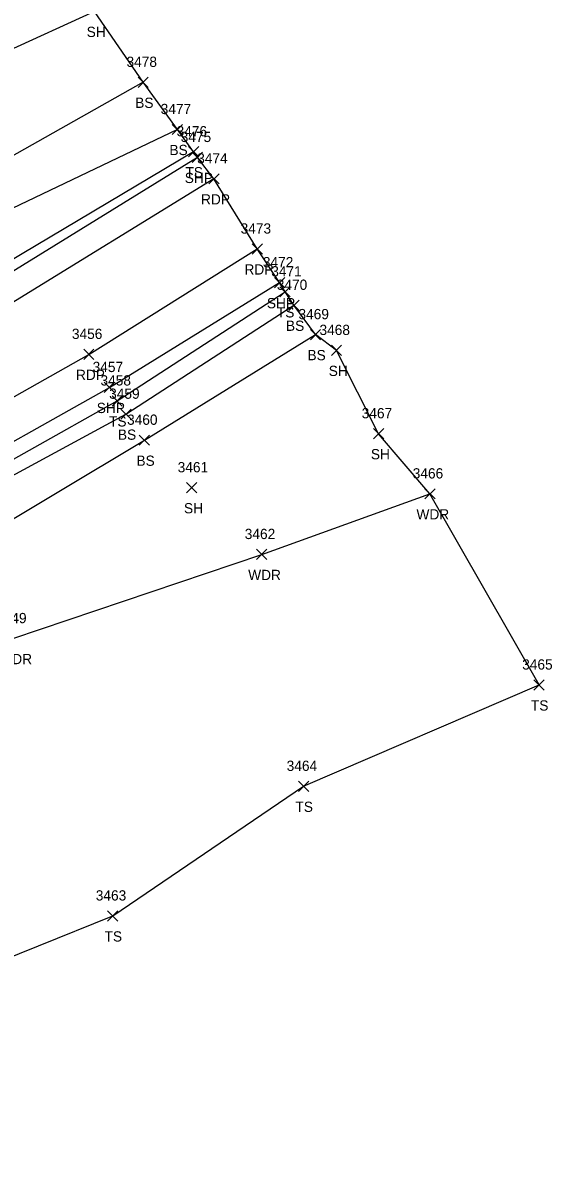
# Model space of a CAD drawing. Extents: x 1623612 to 1625808, y 621345 to 627748.
# Drawn here: x 1625436 to 1625539.3, y 626896.7 to 627120.5 of the extents above; entities that cross this region are included whole.
import ezdxf

# ---------------------------------------------------------------- set-up
doc = ezdxf.new("R2010")
doc.units = 0
for name, color, linetype in [('L_A', 7, 'Continuous'), ('L_I', 7, 'Continuous'), ('L_TIC', 7, 'Continuous'), ('LAWA', 7, 'Continuous'), ('LELB', 7, 'Continuous'), ('LSOGP', 7, 'Continuous'), ('P_A', 7, 'Continuous'), ('P_I', 7, 'Continuous'), ('P_TIC', 7, 'Continuous'), ('PET', 7, 'Continuous'), ('PSP', 7, 'Continuous')]:
    doc.layers.add(name, color=color, linetype=linetype)

msp = doc.modelspace()

# ---------------------------------------------------------------- linework, layer by layer
at = {"layer": 'L_TIC'}
for points in [[(1625458.45, 627107.93), (1625460.45, 627109.93)], [(1625460.45, 627107.93), (1625458.45, 627109.93)], [(1625465.12, 627098.72), (1625467.12, 627100.72)], [(1625467.12, 627098.72), (1625465.12, 627100.72)], [(1625468.29, 627094.38), (1625470.29, 627096.38)], [(1625470.29, 627094.38), (1625468.29, 627096.38)], [(1625486.14, 627067.05), (1625488.14, 627069.05)], [(1625488.14, 627067.05), (1625486.14, 627069.05)], [(1625487.88, 627064.43), (1625489.88, 627066.43)], [(1625489.88, 627064.43), (1625487.88, 627066.43)], [(1625492.08, 627058.7), (1625494.08, 627060.7)], [(1625494.08, 627058.7), (1625492.08, 627060.7)], [(1625496.18, 627055.62), (1625498.18, 627057.62)], [(1625498.18, 627055.62), (1625496.18, 627057.62)], [(1625453.37, 627045.77), (1625455.37, 627047.77)], [(1625455.37, 627045.77), (1625453.37, 627047.77)], [(1625455.07, 627043.18), (1625457.07, 627045.18)], [(1625457.07, 627043.18), (1625455.07, 627045.18)], [(1625504.41, 627039.37), (1625506.41, 627041.37)], [(1625506.41, 627039.37), (1625504.41, 627041.37)], [(1625458.69, 627038.1), (1625460.69, 627040.1)], [(1625460.69, 627038.1), (1625458.69, 627040.1)], [(1625467.92, 627028.83), (1625469.92, 627030.83)], [(1625469.92, 627028.83), (1625467.92, 627030.83)], [(1625514.44, 627027.63), (1625516.44, 627029.63)], [(1625516.44, 627027.63), (1625514.44, 627029.63)], [(1625481.59, 627015.81), (1625483.59, 627017.81)], [(1625483.59, 627015.81), (1625481.59, 627017.81)], [(1625535.74, 626990.35), (1625537.74, 626992.35)], [(1625537.74, 626990.35), (1625535.74, 626992.35)], [(1625489.76, 626970.58), (1625491.76, 626972.58)], [(1625491.76, 626970.58), (1625489.76, 626972.58)], [(1625452.5, 626945.29), (1625454.5, 626947.29)], [(1625454.5, 626945.29), (1625452.5, 626947.29)]]:
    msp.add_lwpolyline(points, dxfattribs=at)
at = {"layer": 'LAWA'}
msp.add_lwpolyline([(1625384.02, 626990.2), (1625434, 627000.4), (1625482.59, 627016.81), (1625515.44, 627028.63)], dxfattribs=at)
at = {"layer": 'LELB'}
for points in [[(1625469.29, 627095.38), (1625429.94, 627072.01), (1625396.47, 627056.33), (1625363.17, 627036.91), (1625324.86, 627017.28), (1625282.83, 626996.93), (1625240.1, 626976.36), (1625200.92, 626956.72), (1625164.36, 626938.31), (1625128.12, 626918.34), (1625094.57, 626896.89), (1625066.91, 626876.48), (1625035.19, 626854.3), (1625018.18, 626859.5), (1625006.28, 626868.94), (1625007.56, 626879.04), (1625022.39, 626921.76), (1625036.67, 626956.96), (1625050.15, 626986.83), (1625070.28, 627027.73), (1625085.48, 627058.74), (1625111, 627101.13), (1625130.83, 627129.7)], [(1625459.45, 627108.93), (1625422.64, 627088.23), (1625389.38, 627068.23), (1625357.1, 627050.98), (1625318.54, 627029.39), (1625278.3, 627010.79), (1625234, 626989.32), (1625195.14, 626971.7)], [(1625466.12, 627099.72), (1625426.45, 627080.76), (1625391.19, 627065.04), (1625359.75, 627046.45), (1625320.22, 627026.23), (1625279.53, 627006.16), (1625236.1, 626985.25), (1625196.36, 626969.39), (1625155.89, 626955.67), (1625118.73, 626941.79)], [(1625407.31, 627018.21), (1625420.07, 627027.54), (1625454.37, 627046.77), (1625487.14, 627068.05)], [(1625407.31, 627018.21), (1625420.73, 627025.04), (1625456.07, 627044.18), (1625488.88, 627065.43)], [(1625383.56, 626996.16), (1625425.88, 627018.88), (1625459.69, 627039.1), (1625493.08, 627059.7)], [(1625083.53, 626780.74), (1625137.04, 626804.12), (1625178.43, 626816.77), (1625245.42, 626840.4), (1625308.04, 626871.64), (1625357.38, 626894.72), (1625395.36, 626919.42), (1625409.95, 626928.75), (1625453.5, 626946.29), (1625490.76, 626971.58), (1625536.74, 626991.35)]]:
    msp.add_lwpolyline(points, dxfattribs=at)
at = {"layer": 'LSOGP'}
msp.add_lwpolyline([(1625409.95, 626928.75), (1625453.5, 626946.29), (1625490.76, 626971.58), (1625536.74, 626991.35), (1625515.44, 627028.63), (1625505.41, 627040.37), (1625497.18, 627056.62), (1625493.08, 627059.7), (1625488.88, 627065.43), (1625487.14, 627068.05), (1625486.07, 627069.84), (1625481.73, 627076.41), (1625473.25, 627090.09), (1625470.03, 627094.27), (1625469.29, 627095.38), (1625466.12, 627099.72), (1625459.45, 627108.93), (1625449.92, 627122.76), (1625415.15, 627106.89)], dxfattribs=at)
at = {"layer": 'P_TIC'}
for points in [[(1625469.03, 627093.27), (1625471.03, 627095.27)], [(1625471.03, 627093.27), (1625469.03, 627095.27)], [(1625472.25, 627089.09), (1625474.25, 627091.09)], [(1625474.25, 627089.09), (1625472.25, 627091.09)], [(1625480.73, 627075.41), (1625482.73, 627077.41)], [(1625482.73, 627075.41), (1625480.73, 627077.41)], [(1625485.07, 627068.84), (1625487.07, 627070.84)], [(1625487.07, 627068.84), (1625485.07, 627070.84)], [(1625447.84, 627054.85), (1625449.84, 627056.85)], [(1625449.84, 627054.85), (1625447.84, 627056.85)], [(1625451.84, 627048.39), (1625453.84, 627050.39)], [(1625453.84, 627048.39), (1625451.84, 627050.39)]]:
    msp.add_lwpolyline(points, dxfattribs=at)
at = {"layer": 'PET'}
for points in [[(1625473.25, 627090.09), (1625432.8, 627065.24), (1625401.59, 627047.56), (1625365.67, 627029.01), (1625328.14, 627010.31), (1625285.33, 626989.61), (1625243.69, 626969.41), (1625203.66, 626950.01), (1625167.56, 626931.17), (1625131.52, 626910.23), (1625100.02, 626889.97), (1625071.13, 626869.72), (1625042.82, 626845.85)], [(1625300.42, 626978.92), (1625335.49, 626995.75), (1625373.33, 627014.59), (1625415.24, 627036.91), (1625448.84, 627055.85), (1625481.73, 627076.41)]]:
    msp.add_lwpolyline(points, dxfattribs=at)
at = {"layer": 'PSP'}
for points in [[(1625470.03, 627094.27), (1625430.53, 627069.96), (1625398.71, 627053.07), (1625363.72, 627035.1), (1625325.83, 627015.73), (1625283.17, 626995.05), (1625241.24, 626974.73), (1625201.61, 626954.83)], [(1625205.02, 626923.68), (1625245.42, 626943.67), (1625294.34, 626967.43), (1625337.44, 626988.32), (1625376.43, 627007.53), (1625418.78, 627030.28), (1625452.84, 627049.39), (1625486.07, 627069.84)]]:
    msp.add_lwpolyline(points, dxfattribs=at)

# ---------------------------------------------------------------- texts
at = {"layer": 'L_A'}
for s, p in [('SH', (1625448.41, 627117.76)), ('BS', (1625457.89, 627103.93)), ('BS', (1625464.57, 627094.72)), ('TS', (1625467.7, 627090.38)), ('TS', (1625485.55, 627063.05)), ('BS', (1625487.32, 627060.43)), ('BS', (1625491.52, 627054.7)), ('SH', (1625495.67, 627051.62)), ('TS', (1625452.78, 627041.77)), ('BS', (1625454.51, 627039.18)), ('BS', (1625458.13, 627034.1)), ('SH', (1625503.9, 627035.37)), ('SH', (1625467.41, 627024.83)), ('WDR', (1625512.8, 627023.63)), ('WDR', (1625479.95, 627011.81)), ('WDR', (1625431.36, 626995.4)), ('TS', (1625535.15, 626986.35)), ('TS', (1625489.17, 626966.58)), ('TS', (1625451.91, 626941.29))]:
    msp.add_text(s, height=2, dxfattribs=at).set_placement(p)
at = {"layer": 'L_I'}
for s, p in [('3478', (1625456.19, 627111.93)), ('3477', (1625462.86, 627102.72)), ('3476', (1625465.97, 627098.38)), ('3471', (1625484.45, 627071.05)), ('3470', (1625485.53, 627068.43)), ('3469', (1625489.76, 627062.7)), ('3468', (1625493.87, 627059.62)), ('3458', (1625451.11, 627049.77)), ('3459', (1625452.8, 627047.18)), ('3467', (1625502.11, 627043.37)), ('3460', (1625456.3, 627042.1)), ('3461', (1625466.18, 627032.83)), ('3466', (1625512.07, 627031.63)), ('3462', (1625479.28, 627019.81)), ('3449', (1625430.73, 627003.4)), ('3465', (1625533.44, 626994.35)), ('3464', (1625487.46, 626974.58)), ('3463', (1625450.19, 626949.29))]:
    msp.add_text(s, height=2, dxfattribs=at).set_placement(p)
at = {"layer": 'P_A'}
for s, p in [('SHP', (1625467.56, 627089.27)), ('RDP', (1625470.74, 627085.09)), ('RDP', (1625479.22, 627071.41)), ('SHP', (1625483.6, 627064.84)), ('RDP', (1625446.33, 627050.85)), ('SHP', (1625450.38, 627044.39))]:
    msp.add_text(s, height=2, dxfattribs=at).set_placement(p)
at = {"layer": 'P_I'}
for s, p in [('3475', (1625466.77, 627097.27)), ('3474', (1625469.99, 627093.09)), ('3473', (1625478.47, 627079.41)), ('3472', (1625482.81, 627072.84)), ('3456', (1625445.53, 627058.85)), ('3457', (1625449.58, 627052.39))]:
    msp.add_text(s, height=2, dxfattribs=at).set_placement(p)

doc.saveas('drawing.dxf')
